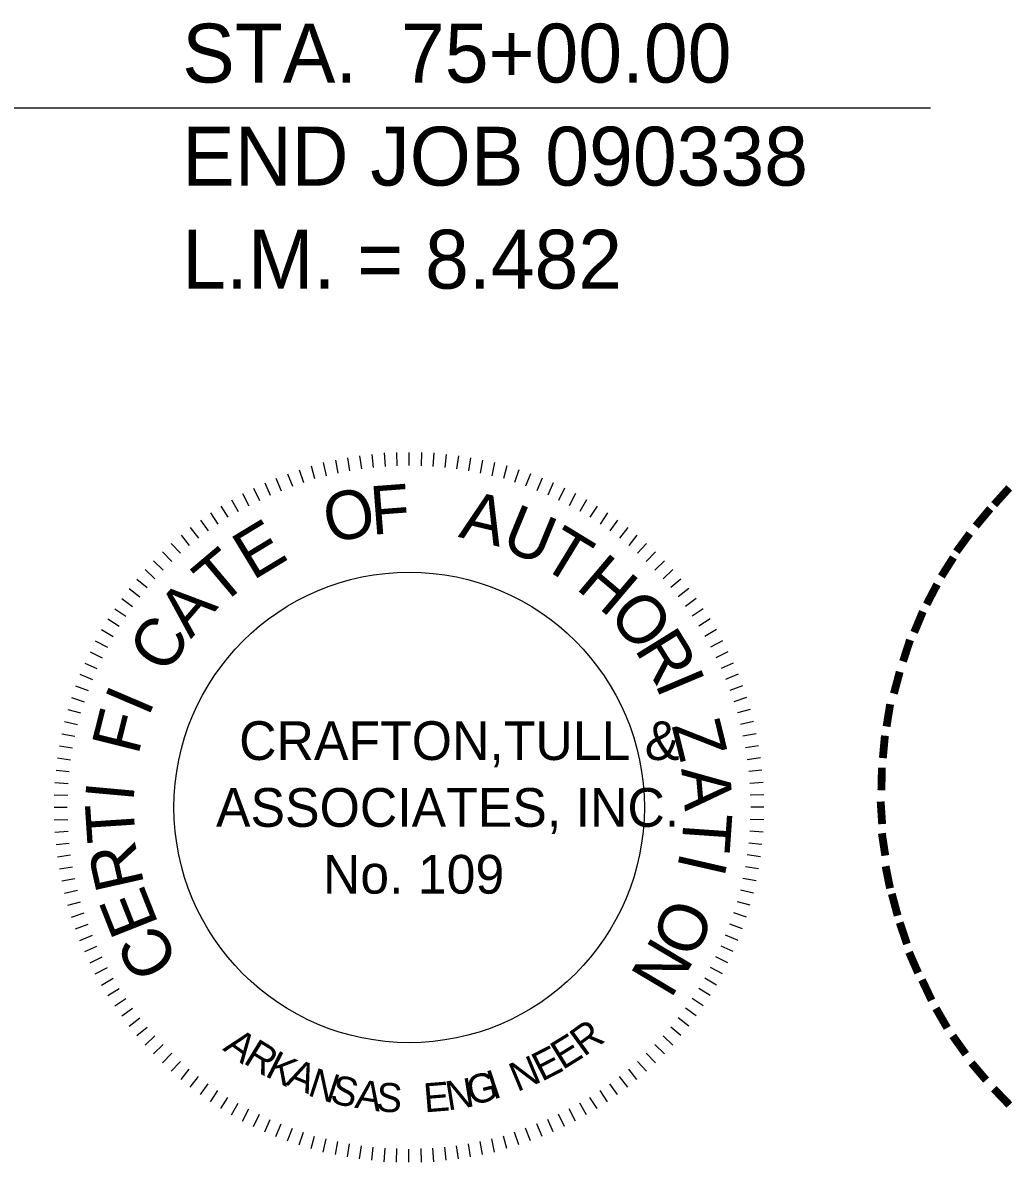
# Model space of a CAD drawing. Extents: x 309389.3 to 309420.2, y 336441.4 to 336461.2.
# Drawn here: x 309413.035 to 309416.817, y 336442.555 to 336446.909 of the extents above; entities that cross this region are included whole.
import ezdxf

# ---------------------------------------------------------------- set-up
doc = ezdxf.new("R2010")
doc.units = 0
doc.layers.add('R_Fin Surface', color=7, linetype='Continuous')
doc.layers.add('R_Temp Easement', color=7, linetype='Continuous')

msp = doc.modelspace()

# ---------------------------------------------------------------- linework, layer by layer
at = {"layer": 'R_Fin Surface'}
msp.add_line((309412.7877, 336446.5841), (309416.5052, 336446.5841), dxfattribs=at)
at = {"layer": 'R_Temp Easement'}
for p, q in [((309414.2302, 336445.2377), (309414.2395, 336445.1878)), ((309414.2765, 336445.247), (309414.2839, 336445.197)), ((309414.3227, 336445.2544), (309414.3301, 336445.2044)), ((309414.369, 336445.2599), (309414.3745, 336445.21)), ((309414.4171, 336445.2655), (309414.4208, 336445.2137)), ((309414.4633, 336445.2673), (309414.4652, 336445.2155)), ((309414.5114, 336445.2673), (309414.5114, 336445.2174)), ((309414.5595, 336445.2673), (309414.5577, 336445.2155)), ((309414.6058, 336445.2655), (309414.6021, 336445.2137)), ((309414.6539, 336445.2599), (309414.6483, 336445.21)), ((309414.7001, 336445.2544), (309414.6927, 336445.2044)), ((309414.7464, 336445.247), (309414.739, 336445.197)), ((309414.7926, 336445.2377), (309414.7834, 336445.1878)), ((309414.0915, 336445.2007), (309414.1081, 336445.1526)), ((309414.1377, 336445.2155), (309414.1507, 336445.1674)), ((309414.184, 336445.2285), (309414.1951, 336445.1785)), ((309414.8389, 336445.2285), (309414.8278, 336445.1785)), ((309414.8851, 336445.2155), (309414.8722, 336445.1674)), ((309414.9314, 336445.2007), (309414.9147, 336445.1526)), ((309413.9601, 336445.1508), (309413.9805, 336445.1045)), ((309414.0027, 336445.1693), (309414.023, 336445.1212)), ((309414.0471, 336445.1859), (309414.0656, 336445.1378)), ((309414.9758, 336445.1859), (309414.9573, 336445.1378)), ((309415.0202, 336445.1693), (309414.9998, 336445.1212)), ((309415.0627, 336445.1508), (309415.0424, 336445.1045)), ((309413.875, 336445.1101), (309413.8991, 336445.0638)), ((309413.9176, 336445.1304), (309413.9398, 336445.0842)), ((309415.1053, 336445.1304), (309415.0831, 336445.0842)), ((309415.1478, 336445.1101), (309415.1238, 336445.0638)), ((309413.7918, 336445.062), (309413.8195, 336445.0194)), ((309413.8325, 336445.086), (309413.8584, 336445.0416)), ((309415.1904, 336445.086), (309415.1645, 336445.0416)), ((309415.2311, 336445.062), (309415.2033, 336445.0194)), ((309413.7529, 336445.0361), (309413.7807, 336444.9935)), ((309415.2699, 336445.0361), (309415.2422, 336444.9935)), ((309413.6752, 336444.9806), (309413.7067, 336444.9399)), ((309413.7141, 336445.0083), (309413.7437, 336444.9676)), ((309415.3088, 336445.0083), (309415.2792, 336444.9676)), ((309415.3476, 336444.9806), (309415.3162, 336444.9399)), ((309413.6401, 336444.951), (309413.6715, 336444.9121)), ((309415.3828, 336444.951), (309415.3513, 336444.9121)), ((309413.5698, 336444.8881), (309413.6049, 336444.8511)), ((309413.6031, 336444.9195), (309413.6382, 336444.8825)), ((309415.4198, 336444.9195), (309415.3846, 336444.8825)), ((309415.4531, 336444.8881), (309415.4179, 336444.8511)), ((309413.5346, 336444.8529), (309413.5716, 336444.8178)), ((309415.4882, 336444.8529), (309415.4512, 336444.8178)), ((309413.5032, 336444.8196), (309413.5402, 336444.7845)), ((309415.5197, 336444.8196), (309415.4827, 336444.7845)), ((309413.4717, 336444.7826), (309413.5106, 336444.7512)), ((309415.5511, 336444.7826), (309415.5123, 336444.7512)), ((309413.4421, 336444.7475), (309413.4828, 336444.716)), ((309415.5807, 336444.7475), (309415.54, 336444.716)), ((309413.3866, 336444.6698), (309413.4292, 336444.642)), ((309413.4144, 336444.7086), (309413.4551, 336444.679)), ((309415.6085, 336444.7086), (309415.5678, 336444.679)), ((309415.6362, 336444.6698), (309415.5937, 336444.642)), ((309413.3607, 336444.6309), (309413.4033, 336444.6032)), ((309415.6621, 336444.6309), (309415.6196, 336444.6032)), ((309413.3367, 336444.5902), (309413.3811, 336444.5643)), ((309415.6862, 336444.5902), (309415.6418, 336444.5643)), ((309413.3126, 336444.5477), (309413.3589, 336444.5236)), ((309415.7102, 336444.5477), (309415.664, 336444.5236)), ((309413.2923, 336444.5051), (309413.3385, 336444.4829)), ((309415.7306, 336444.5051), (309415.6843, 336444.4829)), ((309413.2719, 336444.4626), (309413.3182, 336444.4422)), ((309415.7509, 336444.4626), (309415.7047, 336444.4422)), ((309413.2534, 336444.42), (309413.3015, 336444.3997)), ((309415.7694, 336444.42), (309415.7213, 336444.3997)), ((309413.2368, 336444.3756), (309413.2849, 336444.3571)), ((309415.7861, 336444.3756), (309415.738, 336444.3571)), ((309413.222, 336444.3312), (309413.2701, 336444.3146)), ((309415.8009, 336444.3312), (309415.7528, 336444.3146)), ((309413.2072, 336444.285), (309413.2553, 336444.272)), ((309415.8157, 336444.285), (309415.7676, 336444.272)), ((309413.1942, 336444.2387), (309413.2442, 336444.2276)), ((309415.8286, 336444.2387), (309415.7787, 336444.2276)), ((309413.185, 336444.1925), (309413.2349, 336444.1832)), ((309415.8379, 336444.1925), (309415.7879, 336444.1832)), ((309413.1757, 336444.1462), (309413.2257, 336444.1388)), ((309415.8471, 336444.1462), (309415.7972, 336444.1388)), ((309413.1683, 336444.1), (309413.2183, 336444.0926)), ((309415.8545, 336444.1), (309415.8046, 336444.0926)), ((309413.1628, 336444.0537), (309413.2127, 336444.0482)), ((309415.8601, 336444.0537), (309415.8101, 336444.0482)), ((309413.1572, 336444.0056), (309413.209, 336444.0019)), ((309415.8656, 336444.0056), (309415.8138, 336444.0019)), ((309413.1554, 336443.9594), (309413.2072, 336443.9575)), ((309415.8675, 336443.9594), (309415.8157, 336443.9575)), ((309413.1554, 336443.9113), (309413.2053, 336443.9113)), ((309415.8675, 336443.9113), (309415.8175, 336443.9113)), ((309413.1554, 336443.8632), (309413.2072, 336443.865)), ((309415.8675, 336443.8632), (309415.8157, 336443.865)), ((309413.1572, 336443.8169), (309413.209, 336443.8206)), ((309415.8656, 336443.8169), (309415.8138, 336443.8206)), ((309413.1628, 336443.7688), (309413.2127, 336443.7744)), ((309415.8601, 336443.7688), (309415.8101, 336443.7744)), ((309413.1683, 336443.7226), (309413.2183, 336443.73)), ((309415.8545, 336443.7226), (309415.8046, 336443.73)), ((309413.1757, 336443.6763), (309413.2257, 336443.6837)), ((309415.8471, 336443.6763), (309415.7972, 336443.6837)), ((309413.185, 336443.6301), (309413.2349, 336443.6393)), ((309415.8379, 336443.6301), (309415.7879, 336443.6393)), ((309413.1942, 336443.5838), (309413.2442, 336443.5949)), ((309415.8286, 336443.5838), (309415.7787, 336443.5949)), ((309413.2072, 336443.5376), (309413.2553, 336443.5505)), ((309415.8157, 336443.5376), (309415.7676, 336443.5505)), ((309413.222, 336443.4913), (309413.2701, 336443.508)), ((309415.8009, 336443.4913), (309415.7528, 336443.508)), ((309413.2368, 336443.4469), (309413.2849, 336443.4654)), ((309415.7861, 336443.4469), (309415.738, 336443.4654)), ((309413.2534, 336443.4025), (309413.3015, 336443.4229)), ((309415.7694, 336443.4025), (309415.7213, 336443.4229)), ((309413.2719, 336443.36), (309413.3182, 336443.3803)), ((309415.7509, 336443.36), (309415.7047, 336443.3803)), ((309413.2923, 336443.3174), (309413.3385, 336443.3396)), ((309415.7306, 336443.3174), (309415.6843, 336443.3396)), ((309413.3126, 336443.2749), (309413.3589, 336443.2989)), ((309415.7102, 336443.2749), (309415.664, 336443.2989)), ((309413.3367, 336443.2323), (309413.3811, 336443.2582)), ((309415.6862, 336443.2323), (309415.6418, 336443.2582)), ((309413.3607, 336443.1916), (309413.4033, 336443.2194)), ((309415.6621, 336443.1916), (309415.6196, 336443.2194)), ((309413.3866, 336443.1528), (309413.4292, 336443.1805)), ((309415.6362, 336443.1528), (309415.5937, 336443.1805)), ((309413.4144, 336443.1139), (309413.4551, 336443.1435)), ((309413.4421, 336443.0751), (309413.4828, 336443.1065)), ((309415.5807, 336443.0751), (309415.54, 336443.1065)), ((309415.6085, 336443.1139), (309415.5678, 336443.1435)), ((309413.4717, 336443.0399), (309413.5106, 336443.0714)), ((309415.5511, 336443.0399), (309415.5123, 336443.0714)), ((309413.5032, 336443.0029), (309413.5402, 336443.0381)), ((309415.5197, 336443.0029), (309415.4827, 336443.0381)), ((309413.5346, 336442.9696), (309413.5716, 336443.0048)), ((309413.5698, 336442.9345), (309413.6049, 336442.9715)), ((309415.4531, 336442.9345), (309415.4179, 336442.9715)), ((309415.4882, 336442.9696), (309415.4512, 336443.0048)), ((309413.6031, 336442.903), (309413.6382, 336442.94)), ((309415.4198, 336442.903), (309415.3846, 336442.94)), ((309413.6401, 336442.8716), (309413.6715, 336442.9104)), ((309413.6752, 336442.842), (309413.7067, 336442.8827)), ((309415.3476, 336442.842), (309415.3162, 336442.8827)), ((309415.3828, 336442.8716), (309415.3513, 336442.9104)), ((309413.7141, 336442.8142), (309413.7437, 336442.8549)), ((309415.3088, 336442.8142), (309415.2792, 336442.8549)), ((309413.7529, 336442.7865), (309413.7807, 336442.829)), ((309413.7918, 336442.7606), (309413.8195, 336442.8031)), ((309415.2311, 336442.7606), (309415.2033, 336442.8031)), ((309415.2699, 336442.7865), (309415.2422, 336442.829)), ((309413.8325, 336442.7365), (309413.8584, 336442.7809)), ((309413.875, 336442.7125), (309413.8991, 336442.7587)), ((309415.1478, 336442.7125), (309415.1238, 336442.7587)), ((309415.1904, 336442.7365), (309415.1645, 336442.7809)), ((309413.9176, 336442.6921), (309413.9398, 336442.7384)), ((309413.9601, 336442.6718), (309413.9805, 336442.718)), ((309415.0627, 336442.6718), (309415.0424, 336442.718)), ((309415.1053, 336442.6921), (309415.0831, 336442.7384)), ((309414.0027, 336442.6533), (309414.023, 336442.7014)), ((309414.0471, 336442.6366), (309414.0656, 336442.6847)), ((309414.0915, 336442.6218), (309414.1081, 336442.6699)), ((309414.9314, 336442.6218), (309414.9147, 336442.6699)), ((309414.9758, 336442.6366), (309414.9573, 336442.6847)), ((309415.0202, 336442.6533), (309414.9998, 336442.7014)), ((309414.1377, 336442.607), (309414.1507, 336442.6551)), ((309414.184, 336442.5941), (309414.1951, 336442.644)), ((309414.2302, 336442.5848), (309414.2395, 336442.6348)), ((309414.2765, 336442.5756), (309414.2839, 336442.6255)), ((309414.7464, 336442.5756), (309414.739, 336442.6255)), ((309414.7926, 336442.5848), (309414.7834, 336442.6348)), ((309414.8389, 336442.5941), (309414.8278, 336442.644)), ((309414.8851, 336442.607), (309414.8722, 336442.6551)), ((309414.3227, 336442.5682), (309414.3301, 336442.6181)), ((309414.369, 336442.5626), (309414.3745, 336442.6126)), ((309414.4171, 336442.5571), (309414.4208, 336442.6089)), ((309414.4633, 336442.5552), (309414.4652, 336442.607)), ((309414.5114, 336442.5552), (309414.5114, 336442.6052)), ((309414.5595, 336442.5552), (309414.5577, 336442.607)), ((309414.6058, 336442.5571), (309414.6021, 336442.6089)), ((309414.6539, 336442.5626), (309414.6483, 336442.6126)), ((309414.7001, 336442.5682), (309414.6927, 336442.6181))]:
    msp.add_line(p, q, dxfattribs=at)
msp.add_circle((309414.5122, 336443.9108), 0.8989, dxfattribs=at)

# ---------------------------------------------------------------- texts
at = {"layer": 'R_Fin Surface'}
for s, p in [('STA.  75+00.00', (309413.6449, 336446.6807)), ('END JOB 090338', (309413.6449, 336446.2869)), ('L.M. = 8.482', (309413.6449, 336445.8932))]:
    msp.add_text(s, height=0.225, dxfattribs=at).set_placement(p)
at = {"layer": 'R_Temp Easement'}
for s, height, rotation, p in [('F', 0.185, 4.3732, (309414.3698, 336444.9524)), ('O', 0.185, 13.3113, (309414.2088, 336444.9172)), ('A', 0.185, 346.4969, (309414.6972, 336444.945)), ('-', 0.2638, 48.0254, (309416.8133, 336444.9882)), ('U', 0.185, 337.5588, (309414.8563, 336444.9024)), ('-', 0.2637, 50.2166, (309416.7461, 336444.9088)), ('E', 0.185, 31.1876, (309413.9147, 336444.7766)), ('T', 0.185, 328.6206, (309415.0062, 336444.8358)), ('-', 0.2638, 53.8349, (309416.6769, 336444.8152)), ('T', 0.185, 40.1257, (309413.7889, 336444.6749)), ('H', 0.185, 319.6825, (309415.1449, 336444.7489)), ('-', 0.2638, 57.673, (309416.624, 336444.7257)), ('-', 0.2637, 62.4738, (309416.5732, 336444.626)), ('A', 0.185, 49.0639, (309413.6779, 336444.5528)), ('O', 0.185, 310.7444, (309415.267, 336444.6416)), ('C', 0.185, 58.002, (309413.5872, 336444.414)), ('-', 0.2637, 67.3767, (309416.5304, 336444.5262)), ('R', 0.185, 301.8062, (309415.3706, 336444.5158)), ('-', 0.2637, 71.9969, (309416.4918, 336444.4225)), ('I', 0.185, 292.8681, (309415.4502, 336444.3844)), ('-', 0.2638, 75.0634, (309416.4592, 336444.3044)), ('I', 0.185, 66.9402, (309413.5151, 336444.2531)), ('F', 0.185, 75.8783, (309413.4762, 336444.1069)), ('-', 0.2637, 80.8037, (309416.4348, 336444.1884)), ('Z', 0.185, 283.9299, (309415.5149, 336444.2235)), ('-', 0.2637, 84.7887, (309416.4226, 336444.0745)), ('A', 0.185, 274.9918, (309415.5519, 336444.0588)), ('-', 0.2638, 88.6646, (309416.4185, 336443.9585)), ('I', 0.185, 84.8164, (309413.4577, 336443.9293)), ('-', 0.2637, 93.7983, (309416.4226, 336443.8384)), ('T', 0.185, 93.7546, (309413.467, 336443.7813)), ('T', 0.185, 266.0537, (309415.563, 336443.896)), ('-', 0.2637, 98.5503, (309416.4348, 336443.7265)), ('R', 0.185, 102.6927, (309413.5003, 336443.6167)), ('I', 0.185, 257.1155, (309415.5501, 336443.7462)), ('-', 0.2638, 101.3173, (309416.4531, 336443.6064)), ('E', 0.185, 111.6308, (309413.5558, 336443.465)), ('-', 0.2638, 105.0602, (309416.4816, 336443.5087)), ('O', 0.185, 248.1774, (309415.5075, 336443.576)), ('-', 0.2637, 108.6898, (309416.5162, 336443.407)), ('C', 0.185, 120.569, (309413.6372, 336443.3225)), ('N', 0.185, 239.2393, (309415.4446, 336443.4243)), ('-', 0.2637, 113.6667, (309416.5569, 336443.3052)), ('-', 0.2637, 115.3313, (309416.6078, 336443.2035)), ('-', 0.2638, 120.0495, (309416.6647, 336443.1058)), ('R', 0.111, 36.1806, (309415.1801, 336442.9562)), ('A', 0.111, 324.001, (309413.7963, 336442.9858)), ('R', 0.111, 328.5123, (309413.874, 336442.9359)), ('E', 0.111, 31.6694, (309415.0987, 336442.9063)), ('-', 0.2638, 125.4958, (309416.7319, 336443.0142)), ('K', 0.111, 333.0235, (309413.9572, 336442.8859)), ('E', 0.111, 27.1582, (309415.0191, 336442.8619)), ('A', 0.111, 337.5347, (309414.0368, 336442.8526)), ('N', 0.111, 22.647, (309414.9248, 336442.823)), ('-', 0.2637, 130.3205, (309416.8051, 336442.9227)), ('N', 0.111, 342.0459, (309414.12, 336442.8119)), ('S', 0.111, 346.5572, (309414.2051, 336442.7842)), ('G', 0.111, 13.6245, (309414.7472, 336442.7712)), ('I', 0.111, 18.1357, (309414.8323, 336442.7934)), ('A', 0.111, 351.0684, (309414.3013, 336442.7638)), ('S', 0.111, 355.5796, (309414.3827, 336442.7509)), ('E', 0.111, 4.6021, (309414.5714, 336442.7453)), ('N', 0.111, 9.1133, (309414.6602, 336442.7527)), ('-', 0.2638, 133.8262, (309416.8906, 336442.8331))]:
    msp.add_text(s, height=height, rotation=rotation, dxfattribs=at).set_placement(p)
for s, height, p in [('CRAFTON,TULL &', 0.147996, (309413.8623, 336444.0921)), ('ASSOCIATES, INC.', 0.147996, (309413.7737, 336443.8368)), ('No. 109', 0.148, (309414.1825, 336443.5815))]:
    msp.add_text(s, height=height, dxfattribs=at).set_placement(p)

doc.saveas('drawing.dxf')
